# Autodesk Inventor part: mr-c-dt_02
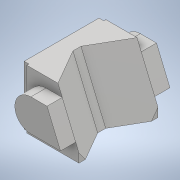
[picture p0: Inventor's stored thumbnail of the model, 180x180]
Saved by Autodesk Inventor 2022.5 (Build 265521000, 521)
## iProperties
Part Number: mr-c-dt_02
Material: 一般
Document SubType Name: Modeling
Designer: ImaoCorp
Density: 1 g/cm^3
Appearance: 既定
Author: ImaoCorp
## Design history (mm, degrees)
feature "mr-c-dt_02"
node "ソリッド1"
